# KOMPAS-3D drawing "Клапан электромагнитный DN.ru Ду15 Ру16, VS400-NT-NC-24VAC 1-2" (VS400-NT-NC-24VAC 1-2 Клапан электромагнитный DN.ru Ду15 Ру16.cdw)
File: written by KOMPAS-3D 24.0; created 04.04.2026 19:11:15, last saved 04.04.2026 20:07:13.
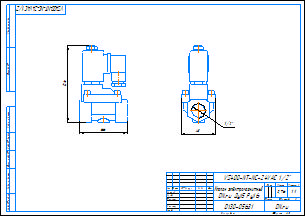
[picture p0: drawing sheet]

Document properties: c3d_UniqueCompID: ef56311e-7521-43dc-8291-0e6108b3d81d; Обозначение: VS400-ET-NC-220VAC 1-2; Наименование: Клапан электромагнитный DN.ru Ду15 Ру16; Автор: artio; Класс точности: c; Знак неуказанной шероховатости: Шероховатость не задана; Рассекать на разрезах: Да; c3d_UniqueCompID: ef56311e-7521-43dc-8291-0e6108b3d81d; Обозначение: VS400-ET-NC-220VAC 3-8; Наименование: Клапан электромагнитный DN.ru Ду10 Ру16; Автор: artio; Класс точности: c; Знак неуказанной шероховатости: Шероховатость не задана; Рассекать на разрезах: Да; Автор: artio; Форматы листов документа: A3; Полное имя файла: VS400-NT-NC-24VAC 1-2 Клапан электромагнитный DN.ru Ду15 Ру16.m3d; Масса: 0.759; Наименование: Клапан электромагнитный DN.ru Ду15 Ру16; Количество листов документа: 1; Примечание: D130-05631

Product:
- Body: Тело 1  | qty 1
    Масса: 1.030062
- Part/product: Клапан электромагнитный DN.ru Ду15 Ру16  | designation VS400-NT-NC-24VAC 1-2
    Масса: 0.759
    Раздел спецификации: Прочие изделия
    Примечание: D130-05631
    additional columns: ef56311e-7521-43dc-8291-0e6108b3d81d; VS400-ET-NC-220VAC 1-2; artio; c; Шероховатость не задана; Да

Views: Вид 1, Спереди, Проекционный вид 2
Referenced files in C:\Users\artio\OneDrive\Рабочий стол\Клапан электромагнитный DN.ru\VS400-ET-NC\VS400-ET-NC-24VDC\: VS400-ET-NC-24VDC 3-8 Клапан электромагнитный DN.ru Ду10 Ру16.m3d
Referenced files in C:\Users\artio\OneDrive\Рабочий стол\Клапан электромагнитный DN.ru\VS400-NT-NC\VS400-NT-NC-24VAC\: VS400-NT-NC-24VAC 1-2 Клапан электромагнитный DN.ru Ду15 Ру16.m3d
Referenced files in C:\Users\artio\OneDrive\Рабочий стол\Клапан электромагнитный DN.ru\VS400-ET-NC\: VS400-ET-NC-24VDC 3-8 Клапан электромагнитный DN.ru Ду10 Ру16.cdw
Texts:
  VS400-NT-NC-24VAC 1-2
  Клапан электромагнитный
  DN.ru Ду15 Ру16
  VS400-NT-NC-24VAC 1/2"
  VS400-NT-NC-24VAC 1/2"-
  Клапан электромагнитный DN.ru Ду15 Ру16
  VS400-NT-NC-24VAC 1-2 Клапан электромагнитный DN.ru Ду15 Ру16
Dimensions and other numbers on the sheet: 0; 3; 2; 4; 48; 1/2"; 66; 106; 1:1; 1; 0,76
